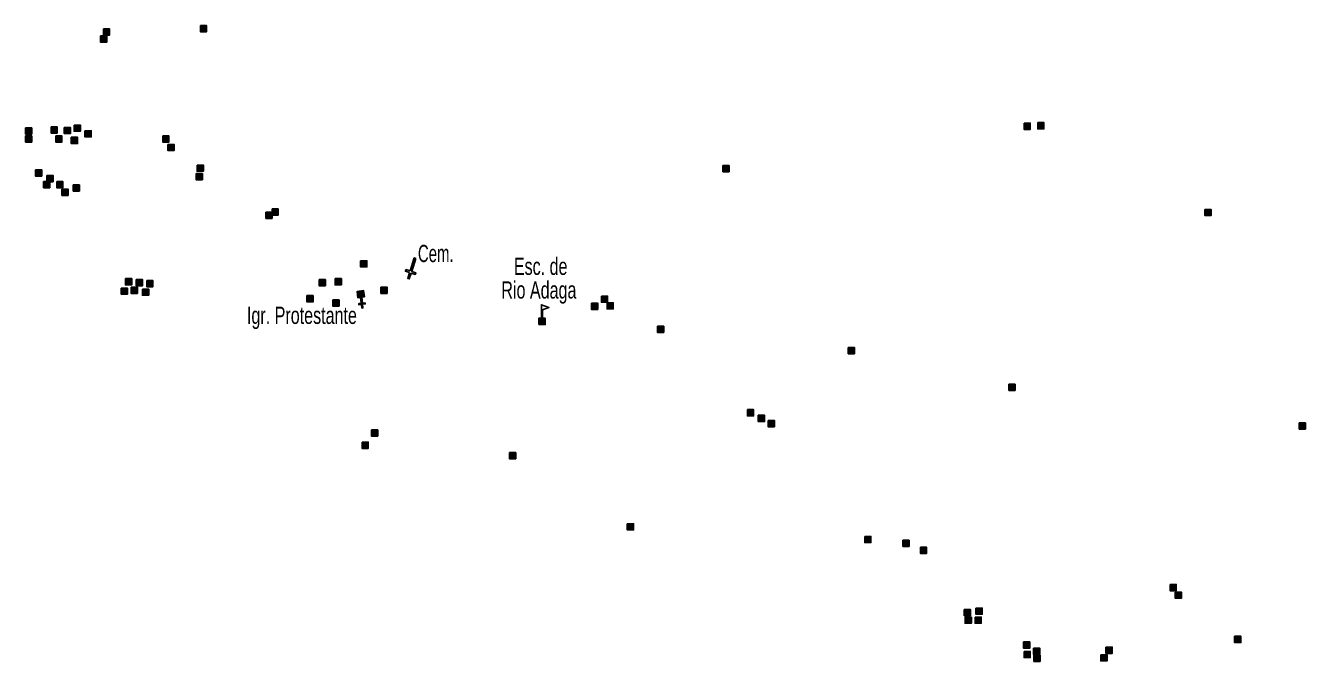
# Model space of a CAD drawing. Extents: x 647.8 to 672.9, y 6929.3 to 6957.3.
# Drawn here: x 666.43 to 672.38, y 6933.27 to 6936.23 of the extents above; entities that cross this region are included whole.
import ezdxf
from ezdxf.enums import TextEntityAlignment as Align

# ---------------------------------------------------------------- set-up
doc = ezdxf.new("R2010")
doc.units = 0
doc.header["$LTSCALE"] = 0.032
for name, color, linetype, lineweight in [('2', 7, 'Continuous', 25), ('20', 7, 'Continuous', 25), ('4', 7, 'Continuous', 25), ('6', 7, 'Continuous', 25)]:
    doc.layers.add(name, color=color, linetype=linetype, lineweight=lineweight)
doc.layers.add('61', color=7, linetype='Continuous')

msp = doc.modelspace()

# ---------------------------------------------------------------- hatches: boundary and pattern name
at = {"layer": '2'}
for points in [[(666.7876, 6936.2175), (666.8166, 6936.2175), (666.8166, 6936.1885), (666.7876, 6936.1885)], [(667.2396, 6936.2328), (667.2686, 6936.2328), (667.2686, 6936.2038), (667.2396, 6936.2038)], [(666.7745, 6936.1845), (666.8035, 6936.1845), (666.8035, 6936.1555), (666.7745, 6936.1555)], [(666.4256, 6935.7567), (666.4546, 6935.7567), (666.4546, 6935.7277), (666.4256, 6935.7277)], [(666.5441, 6935.7611), (666.5731, 6935.7611), (666.5731, 6935.7321), (666.5441, 6935.7321)], [(666.6055, 6935.7589), (666.6345, 6935.7589), (666.6345, 6935.7299), (666.6055, 6935.7299)], [(666.6516, 6935.7699), (666.6806, 6935.7699), (666.6806, 6935.7409), (666.6516, 6935.7409)], [(666.7021, 6935.7436), (666.7311, 6935.7436), (666.7311, 6935.7146), (666.7021, 6935.7146)], [(671.0744, 6935.7787), (671.1034, 6935.7787), (671.1034, 6935.7497), (671.0744, 6935.7497)], [(671.138, 6935.7809), (671.167, 6935.7809), (671.167, 6935.7519), (671.138, 6935.7519)], [(666.4256, 6935.7195), (666.4546, 6935.7195), (666.4546, 6935.6905), (666.4256, 6935.6905)], [(666.566, 6935.7195), (666.595, 6935.7195), (666.595, 6935.6905), (666.566, 6935.6905)], [(666.6384, 6935.7129), (666.6674, 6935.7129), (666.6674, 6935.6839), (666.6384, 6935.6839)], [(667.064, 6935.7195), (667.093, 6935.7195), (667.093, 6935.6905), (667.064, 6935.6905)], [(667.0882, 6935.68), (667.1172, 6935.68), (667.1172, 6935.651), (667.0882, 6935.651)], [(666.4717, 6935.5615), (666.5007, 6935.5615), (666.5007, 6935.5325), (666.4717, 6935.5325)], [(667.2242, 6935.5834), (667.2532, 6935.5834), (667.2532, 6935.5544), (667.2242, 6935.5544)], [(669.6725, 6935.5812), (669.7015, 6935.5812), (669.7015, 6935.5522), (669.6725, 6935.5522)], [(666.509, 6935.5067), (666.538, 6935.5067), (666.538, 6935.4777), (666.509, 6935.4777)], [(666.5244, 6935.5352), (666.5534, 6935.5352), (666.5534, 6935.5062), (666.5244, 6935.5062)], [(666.5704, 6935.5067), (666.5994, 6935.5067), (666.5994, 6935.4777), (666.5704, 6935.4777)], [(667.2198, 6935.5439), (667.2488, 6935.5439), (667.2488, 6935.5149), (667.2198, 6935.5149)], [(666.5946, 6935.4715), (666.6236, 6935.4715), (666.6236, 6935.4425), (666.5946, 6935.4425)], [(666.6472, 6935.4913), (666.6762, 6935.4913), (666.6762, 6935.4623), (666.6472, 6935.4623)], [(667.5445, 6935.3641), (667.5735, 6935.3641), (667.5735, 6935.3351), (667.5445, 6935.3351)], [(667.573, 6935.3794), (667.602, 6935.3794), (667.602, 6935.3504), (667.573, 6935.3504)], [(671.9168, 6935.3772), (671.9458, 6935.3772), (671.9458, 6935.3482), (671.9168, 6935.3482)], [(667.9855, 6935.1381), (668.0145, 6935.1381), (668.0145, 6935.1091), (667.9855, 6935.1091)], [(666.8907, 6935.0547), (666.9197, 6935.0547), (666.9197, 6935.0257), (666.8907, 6935.0257)], [(666.9412, 6935.0503), (666.9702, 6935.0503), (666.9702, 6935.0213), (666.9412, 6935.0213)], [(666.9895, 6935.0459), (667.0185, 6935.0459), (667.0185, 6935.0169), (666.9895, 6935.0169)], [(667.7924, 6935.0503), (667.8214, 6935.0503), (667.8214, 6935.0213), (667.7924, 6935.0213)], [(667.867, 6935.0547), (667.896, 6935.0547), (667.896, 6935.0257), (667.867, 6935.0257)], [(666.871, 6935.0108), (666.9, 6935.0108), (666.9, 6934.9818), (666.871, 6934.9818)], [(666.9171, 6935.0152), (666.9461, 6935.0152), (666.9461, 6934.9862), (666.9171, 6934.9862)], [(666.9697, 6935.0065), (666.9987, 6935.0065), (666.9987, 6934.9775), (666.9697, 6934.9775)], [(667.7354, 6934.9757), (667.7644, 6934.9757), (667.7644, 6934.9467), (667.7354, 6934.9467)], [(668.0798, 6935.0152), (668.1088, 6935.0152), (668.1088, 6934.9862), (668.0798, 6934.9862)], [(669.1065, 6934.9735), (669.1355, 6934.9735), (669.1355, 6934.9445), (669.1065, 6934.9445)], [(667.856, 6934.956), (667.885, 6934.956), (667.885, 6934.927), (667.856, 6934.927)], [(669.0604, 6934.9406), (669.0894, 6934.9406), (669.0894, 6934.9116), (669.0604, 6934.9116)], [(669.1328, 6934.9428), (669.1618, 6934.9428), (669.1618, 6934.9138), (669.1328, 6934.9138)], [(669.3676, 6934.8331), (669.3966, 6934.8331), (669.3966, 6934.8041), (669.3676, 6934.8041)], [(670.2561, 6934.7344), (670.2851, 6934.7344), (670.2851, 6934.7054), (670.2561, 6934.7054)], [(671.0042, 6934.5633), (671.0332, 6934.5633), (671.0332, 6934.5343), (671.0042, 6934.5343)], [(669.7866, 6934.4448), (669.8156, 6934.4448), (669.8156, 6934.4158), (669.7866, 6934.4158)], [(669.8371, 6934.4185), (669.8661, 6934.4185), (669.8661, 6934.3895), (669.8371, 6934.3895)], [(669.8831, 6934.3944), (669.9121, 6934.3944), (669.9121, 6934.3654), (669.8831, 6934.3654)], [(672.3556, 6934.3834), (672.3846, 6934.3834), (672.3846, 6934.3544), (672.3556, 6934.3544)], [(668.0359, 6934.3505), (668.0649, 6934.3505), (668.0649, 6934.3215), (668.0359, 6934.3215)], [(667.992, 6934.2935), (668.021, 6934.2935), (668.021, 6934.2645), (667.992, 6934.2645)], [(668.6787, 6934.2452), (668.7077, 6934.2452), (668.7077, 6934.2162), (668.6787, 6934.2162)], [(669.2272, 6933.9139), (669.2562, 6933.9139), (669.2562, 6933.8849), (669.2272, 6933.8849)], [(670.3329, 6933.8547), (670.3619, 6933.8547), (670.3619, 6933.8257), (670.3329, 6933.8257)], [(670.5106, 6933.8371), (670.5396, 6933.8371), (670.5396, 6933.8081), (670.5106, 6933.8081)], [(670.5918, 6933.8042), (670.6208, 6933.8042), (670.6208, 6933.7752), (670.5918, 6933.7752)], [(671.7545, 6933.6309), (671.7835, 6933.6309), (671.7835, 6933.6019), (671.7545, 6933.6019)], [(671.7786, 6933.5958), (671.8076, 6933.5958), (671.8076, 6933.5668), (671.7786, 6933.5668)], [(670.7958, 6933.5146), (670.8248, 6933.5146), (670.8248, 6933.4856), (670.7958, 6933.4856)], [(670.8002, 6933.4795), (670.8292, 6933.4795), (670.8292, 6933.4505), (670.8002, 6933.4505)], [(670.8462, 6933.4795), (670.8752, 6933.4795), (670.8752, 6933.4505), (670.8462, 6933.4505)], [(670.8506, 6933.5212), (670.8796, 6933.5212), (670.8796, 6933.4922), (670.8506, 6933.4922)], [(671.0722, 6933.3633), (671.1012, 6933.3633), (671.1012, 6933.3343), (671.0722, 6933.3343)], [(672.055, 6933.3896), (672.084, 6933.3896), (672.084, 6933.3606), (672.055, 6933.3606)], [(671.0744, 6933.3194), (671.1034, 6933.3194), (671.1034, 6933.2904), (671.0744, 6933.2904)], [(671.1183, 6933.3347), (671.1473, 6933.3347), (671.1473, 6933.3057), (671.1183, 6933.3057)], [(671.1205, 6933.3018), (671.1495, 6933.3018), (671.1495, 6933.2728), (671.1205, 6933.2728)], [(671.432, 6933.304), (671.461, 6933.304), (671.461, 6933.275), (671.432, 6933.275)], [(671.4561, 6933.3391), (671.4851, 6933.3391), (671.4851, 6933.3101), (671.4561, 6933.3101)]]:
    msp.add_hatch(color=256, dxfattribs=at).paths.add_polyline_path(points)
at = {"layer": '4'}
msp.add_hatch(color=256, dxfattribs=at).paths.add_polyline_path([(668.8149, 6934.8407), (668.8149, 6934.8707), (668.8449, 6934.8707), (668.8449, 6934.8407)])
at = {"layer": '6'}
for points in [[(668.0029, 6934.9694), (667.9992, 6934.9991), (667.9695, 6934.9955), (667.9731, 6934.9657)], [(667.9855, 6934.9673), (667.9905, 6934.9678), (667.9938, 6934.9406), (668.0062, 6934.942), (668.0068, 6934.9371), (667.9944, 6934.9356), (667.9966, 6934.9182), (667.9916, 6934.9176), (667.9895, 6934.9349), (667.977, 6934.9335), (667.9765, 6934.9384), (667.9888, 6934.9399)]]:
    msp.add_hatch(color=256, dxfattribs=at).paths.add_polyline_path(points)

# ---------------------------------------------------------------- linework, layer by layer
at = {"layer": '2'}
for points in [[(666.7876, 6936.2175), (666.8166, 6936.2175), (666.8166, 6936.1885), (666.7876, 6936.1885)], [(667.2396, 6936.2328), (667.2686, 6936.2328), (667.2686, 6936.2038), (667.2396, 6936.2038)], [(666.7745, 6936.1845), (666.8035, 6936.1845), (666.8035, 6936.1555), (666.7745, 6936.1555)], [(666.4256, 6935.7567), (666.4546, 6935.7567), (666.4546, 6935.7277), (666.4256, 6935.7277)], [(666.5441, 6935.7611), (666.5731, 6935.7611), (666.5731, 6935.7321), (666.5441, 6935.7321)], [(666.6055, 6935.7589), (666.6345, 6935.7589), (666.6345, 6935.7299), (666.6055, 6935.7299)], [(666.6516, 6935.7699), (666.6806, 6935.7699), (666.6806, 6935.7409), (666.6516, 6935.7409)], [(666.7021, 6935.7436), (666.7311, 6935.7436), (666.7311, 6935.7146), (666.7021, 6935.7146)], [(671.0744, 6935.7787), (671.1034, 6935.7787), (671.1034, 6935.7497), (671.0744, 6935.7497)], [(671.138, 6935.7809), (671.167, 6935.7809), (671.167, 6935.7519), (671.138, 6935.7519)], [(666.4256, 6935.7195), (666.4546, 6935.7195), (666.4546, 6935.6905), (666.4256, 6935.6905)], [(666.566, 6935.7195), (666.595, 6935.7195), (666.595, 6935.6905), (666.566, 6935.6905)], [(666.6384, 6935.7129), (666.6674, 6935.7129), (666.6674, 6935.6839), (666.6384, 6935.6839)], [(667.064, 6935.7195), (667.093, 6935.7195), (667.093, 6935.6905), (667.064, 6935.6905)], [(667.0882, 6935.68), (667.1172, 6935.68), (667.1172, 6935.651), (667.0882, 6935.651)], [(666.4717, 6935.5615), (666.5007, 6935.5615), (666.5007, 6935.5325), (666.4717, 6935.5325)], [(667.2242, 6935.5834), (667.2532, 6935.5834), (667.2532, 6935.5544), (667.2242, 6935.5544)], [(669.6725, 6935.5812), (669.7015, 6935.5812), (669.7015, 6935.5522), (669.6725, 6935.5522)], [(666.509, 6935.5067), (666.538, 6935.5067), (666.538, 6935.4777), (666.509, 6935.4777)], [(666.5244, 6935.5352), (666.5534, 6935.5352), (666.5534, 6935.5062), (666.5244, 6935.5062)], [(666.5704, 6935.5067), (666.5994, 6935.5067), (666.5994, 6935.4777), (666.5704, 6935.4777)], [(667.2198, 6935.5439), (667.2488, 6935.5439), (667.2488, 6935.5149), (667.2198, 6935.5149)], [(666.5946, 6935.4715), (666.6236, 6935.4715), (666.6236, 6935.4425), (666.5946, 6935.4425)], [(666.6472, 6935.4913), (666.6762, 6935.4913), (666.6762, 6935.4623), (666.6472, 6935.4623)], [(667.5445, 6935.3641), (667.5735, 6935.3641), (667.5735, 6935.3351), (667.5445, 6935.3351)], [(667.573, 6935.3794), (667.602, 6935.3794), (667.602, 6935.3504), (667.573, 6935.3504)], [(671.9168, 6935.3772), (671.9458, 6935.3772), (671.9458, 6935.3482), (671.9168, 6935.3482)], [(667.9855, 6935.1381), (668.0145, 6935.1381), (668.0145, 6935.1091), (667.9855, 6935.1091)], [(666.8907, 6935.0547), (666.9197, 6935.0547), (666.9197, 6935.0257), (666.8907, 6935.0257)], [(666.9412, 6935.0503), (666.9702, 6935.0503), (666.9702, 6935.0213), (666.9412, 6935.0213)], [(666.9895, 6935.0459), (667.0185, 6935.0459), (667.0185, 6935.0169), (666.9895, 6935.0169)], [(667.7924, 6935.0503), (667.8214, 6935.0503), (667.8214, 6935.0213), (667.7924, 6935.0213)], [(667.867, 6935.0547), (667.896, 6935.0547), (667.896, 6935.0257), (667.867, 6935.0257)], [(666.871, 6935.0108), (666.9, 6935.0108), (666.9, 6934.9818), (666.871, 6934.9818)], [(666.9171, 6935.0152), (666.9461, 6935.0152), (666.9461, 6934.9862), (666.9171, 6934.9862)], [(666.9697, 6935.0065), (666.9987, 6935.0065), (666.9987, 6934.9775), (666.9697, 6934.9775)], [(667.7354, 6934.9757), (667.7644, 6934.9757), (667.7644, 6934.9467), (667.7354, 6934.9467)], [(668.0798, 6935.0152), (668.1088, 6935.0152), (668.1088, 6934.9862), (668.0798, 6934.9862)], [(669.1065, 6934.9735), (669.1355, 6934.9735), (669.1355, 6934.9445), (669.1065, 6934.9445)], [(667.856, 6934.956), (667.885, 6934.956), (667.885, 6934.927), (667.856, 6934.927)], [(669.0604, 6934.9406), (669.0894, 6934.9406), (669.0894, 6934.9116), (669.0604, 6934.9116)], [(669.1328, 6934.9428), (669.1618, 6934.9428), (669.1618, 6934.9138), (669.1328, 6934.9138)], [(669.3676, 6934.8331), (669.3966, 6934.8331), (669.3966, 6934.8041), (669.3676, 6934.8041)], [(670.2561, 6934.7344), (670.2851, 6934.7344), (670.2851, 6934.7054), (670.2561, 6934.7054)], [(671.0042, 6934.5633), (671.0332, 6934.5633), (671.0332, 6934.5343), (671.0042, 6934.5343)], [(669.7866, 6934.4448), (669.8156, 6934.4448), (669.8156, 6934.4158), (669.7866, 6934.4158)], [(669.8371, 6934.4185), (669.8661, 6934.4185), (669.8661, 6934.3895), (669.8371, 6934.3895)], [(669.8831, 6934.3944), (669.9121, 6934.3944), (669.9121, 6934.3654), (669.8831, 6934.3654)], [(672.3556, 6934.3834), (672.3846, 6934.3834), (672.3846, 6934.3544), (672.3556, 6934.3544)], [(668.0359, 6934.3505), (668.0649, 6934.3505), (668.0649, 6934.3215), (668.0359, 6934.3215)], [(667.992, 6934.2935), (668.021, 6934.2935), (668.021, 6934.2645), (667.992, 6934.2645)], [(668.6787, 6934.2452), (668.7077, 6934.2452), (668.7077, 6934.2162), (668.6787, 6934.2162)], [(669.2272, 6933.9139), (669.2562, 6933.9139), (669.2562, 6933.8849), (669.2272, 6933.8849)], [(670.3329, 6933.8547), (670.3619, 6933.8547), (670.3619, 6933.8257), (670.3329, 6933.8257)], [(670.5106, 6933.8371), (670.5396, 6933.8371), (670.5396, 6933.8081), (670.5106, 6933.8081)], [(670.5918, 6933.8042), (670.6208, 6933.8042), (670.6208, 6933.7752), (670.5918, 6933.7752)], [(671.7545, 6933.6309), (671.7835, 6933.6309), (671.7835, 6933.6019), (671.7545, 6933.6019)], [(671.7786, 6933.5958), (671.8076, 6933.5958), (671.8076, 6933.5668), (671.7786, 6933.5668)], [(670.7958, 6933.5146), (670.8248, 6933.5146), (670.8248, 6933.4856), (670.7958, 6933.4856)], [(670.8002, 6933.4795), (670.8292, 6933.4795), (670.8292, 6933.4505), (670.8002, 6933.4505)], [(670.8462, 6933.4795), (670.8752, 6933.4795), (670.8752, 6933.4505), (670.8462, 6933.4505)], [(670.8506, 6933.5212), (670.8796, 6933.5212), (670.8796, 6933.4922), (670.8506, 6933.4922)], [(671.0722, 6933.3633), (671.1012, 6933.3633), (671.1012, 6933.3343), (671.0722, 6933.3343)], [(672.055, 6933.3896), (672.084, 6933.3896), (672.084, 6933.3606), (672.055, 6933.3606)], [(671.0744, 6933.3194), (671.1034, 6933.3194), (671.1034, 6933.2904), (671.0744, 6933.2904)], [(671.1183, 6933.3347), (671.1473, 6933.3347), (671.1473, 6933.3057), (671.1183, 6933.3057)], [(671.1205, 6933.3018), (671.1495, 6933.3018), (671.1495, 6933.2728), (671.1205, 6933.2728)], [(671.432, 6933.304), (671.461, 6933.304), (671.461, 6933.275), (671.432, 6933.275)], [(671.4561, 6933.3391), (671.4851, 6933.3391), (671.4851, 6933.3101), (671.4561, 6933.3101)]]:
    msp.add_lwpolyline(points, close=True, dxfattribs=at)
at = {"layer": '20'}
for points in [[(668.2429, 6935.1488), (668.2354, 6935.1512), (668.2158, 6935.0908)], [(668.2208, 6935.0802), (668.2399, 6935.0741), (668.2424, 6935.0821), (668.2234, 6935.0883), (668.2429, 6935.1488)], [(668.2158, 6935.0908), (668.1967, 6935.0969), (668.1942, 6935.0888), (668.2132, 6935.0827)], [(668.2132, 6935.0827), (668.2046, 6935.0561), (668.2122, 6935.0536), (668.2208, 6935.0802)]]:
    msp.add_lwpolyline(points, dxfattribs=at)
at = {"layer": '4'}
msp.add_line((668.8274, 6934.8707), (668.8324, 6934.8707), dxfattribs=at)
for points in [[(668.8274, 6934.8707), (668.8274, 6934.9332), (668.8624, 6934.9207), (668.8324, 6934.9102), (668.8324, 6934.8707)], [(668.8149, 6934.8407), (668.8149, 6934.8707), (668.8449, 6934.8707), (668.8449, 6934.8407)]]:
    msp.add_lwpolyline(points, close=True, dxfattribs=at)
at = {"layer": '6'}
for points in [[(668.0029, 6934.9694), (667.9992, 6934.9991), (667.9695, 6934.9955), (667.9731, 6934.9657)], [(667.9855, 6934.9673), (667.9905, 6934.9678), (667.9938, 6934.9406), (668.0062, 6934.942), (668.0068, 6934.9371), (667.9944, 6934.9356), (667.9966, 6934.9182), (667.9916, 6934.9176), (667.9895, 6934.9349), (667.977, 6934.9335), (667.9765, 6934.9384), (667.9888, 6934.9399)]]:
    msp.add_lwpolyline(points, close=True, dxfattribs=at)

# ---------------------------------------------------------------- texts
at = {"layer": '61', "width": 0.65}
msp.add_text('Cem.', height=0.08, dxfattribs=at).set_placement((668.2524, 6935.1319))
at = {"layer": '61', "width": 0.7}
for s, p in [('  Esc. de  ', (668.9904, 6935.0721)), ('Rio Adaga', (668.9904, 6934.9621)), ('Igr. Protestante', (667.9683, 6934.8439))]:
    msp.add_text(s, height=0.08, dxfattribs=at).set_placement(p, align=Align.RIGHT)

doc.saveas('drawing.dxf')
